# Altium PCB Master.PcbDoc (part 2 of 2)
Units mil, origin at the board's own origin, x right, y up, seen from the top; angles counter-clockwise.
Board outline 11420.03 x 8220.01 mil, 2 copper layers (Top Layer, Bottom Layer); 224 components, 0 nets, 1169 pads, 54 vias.
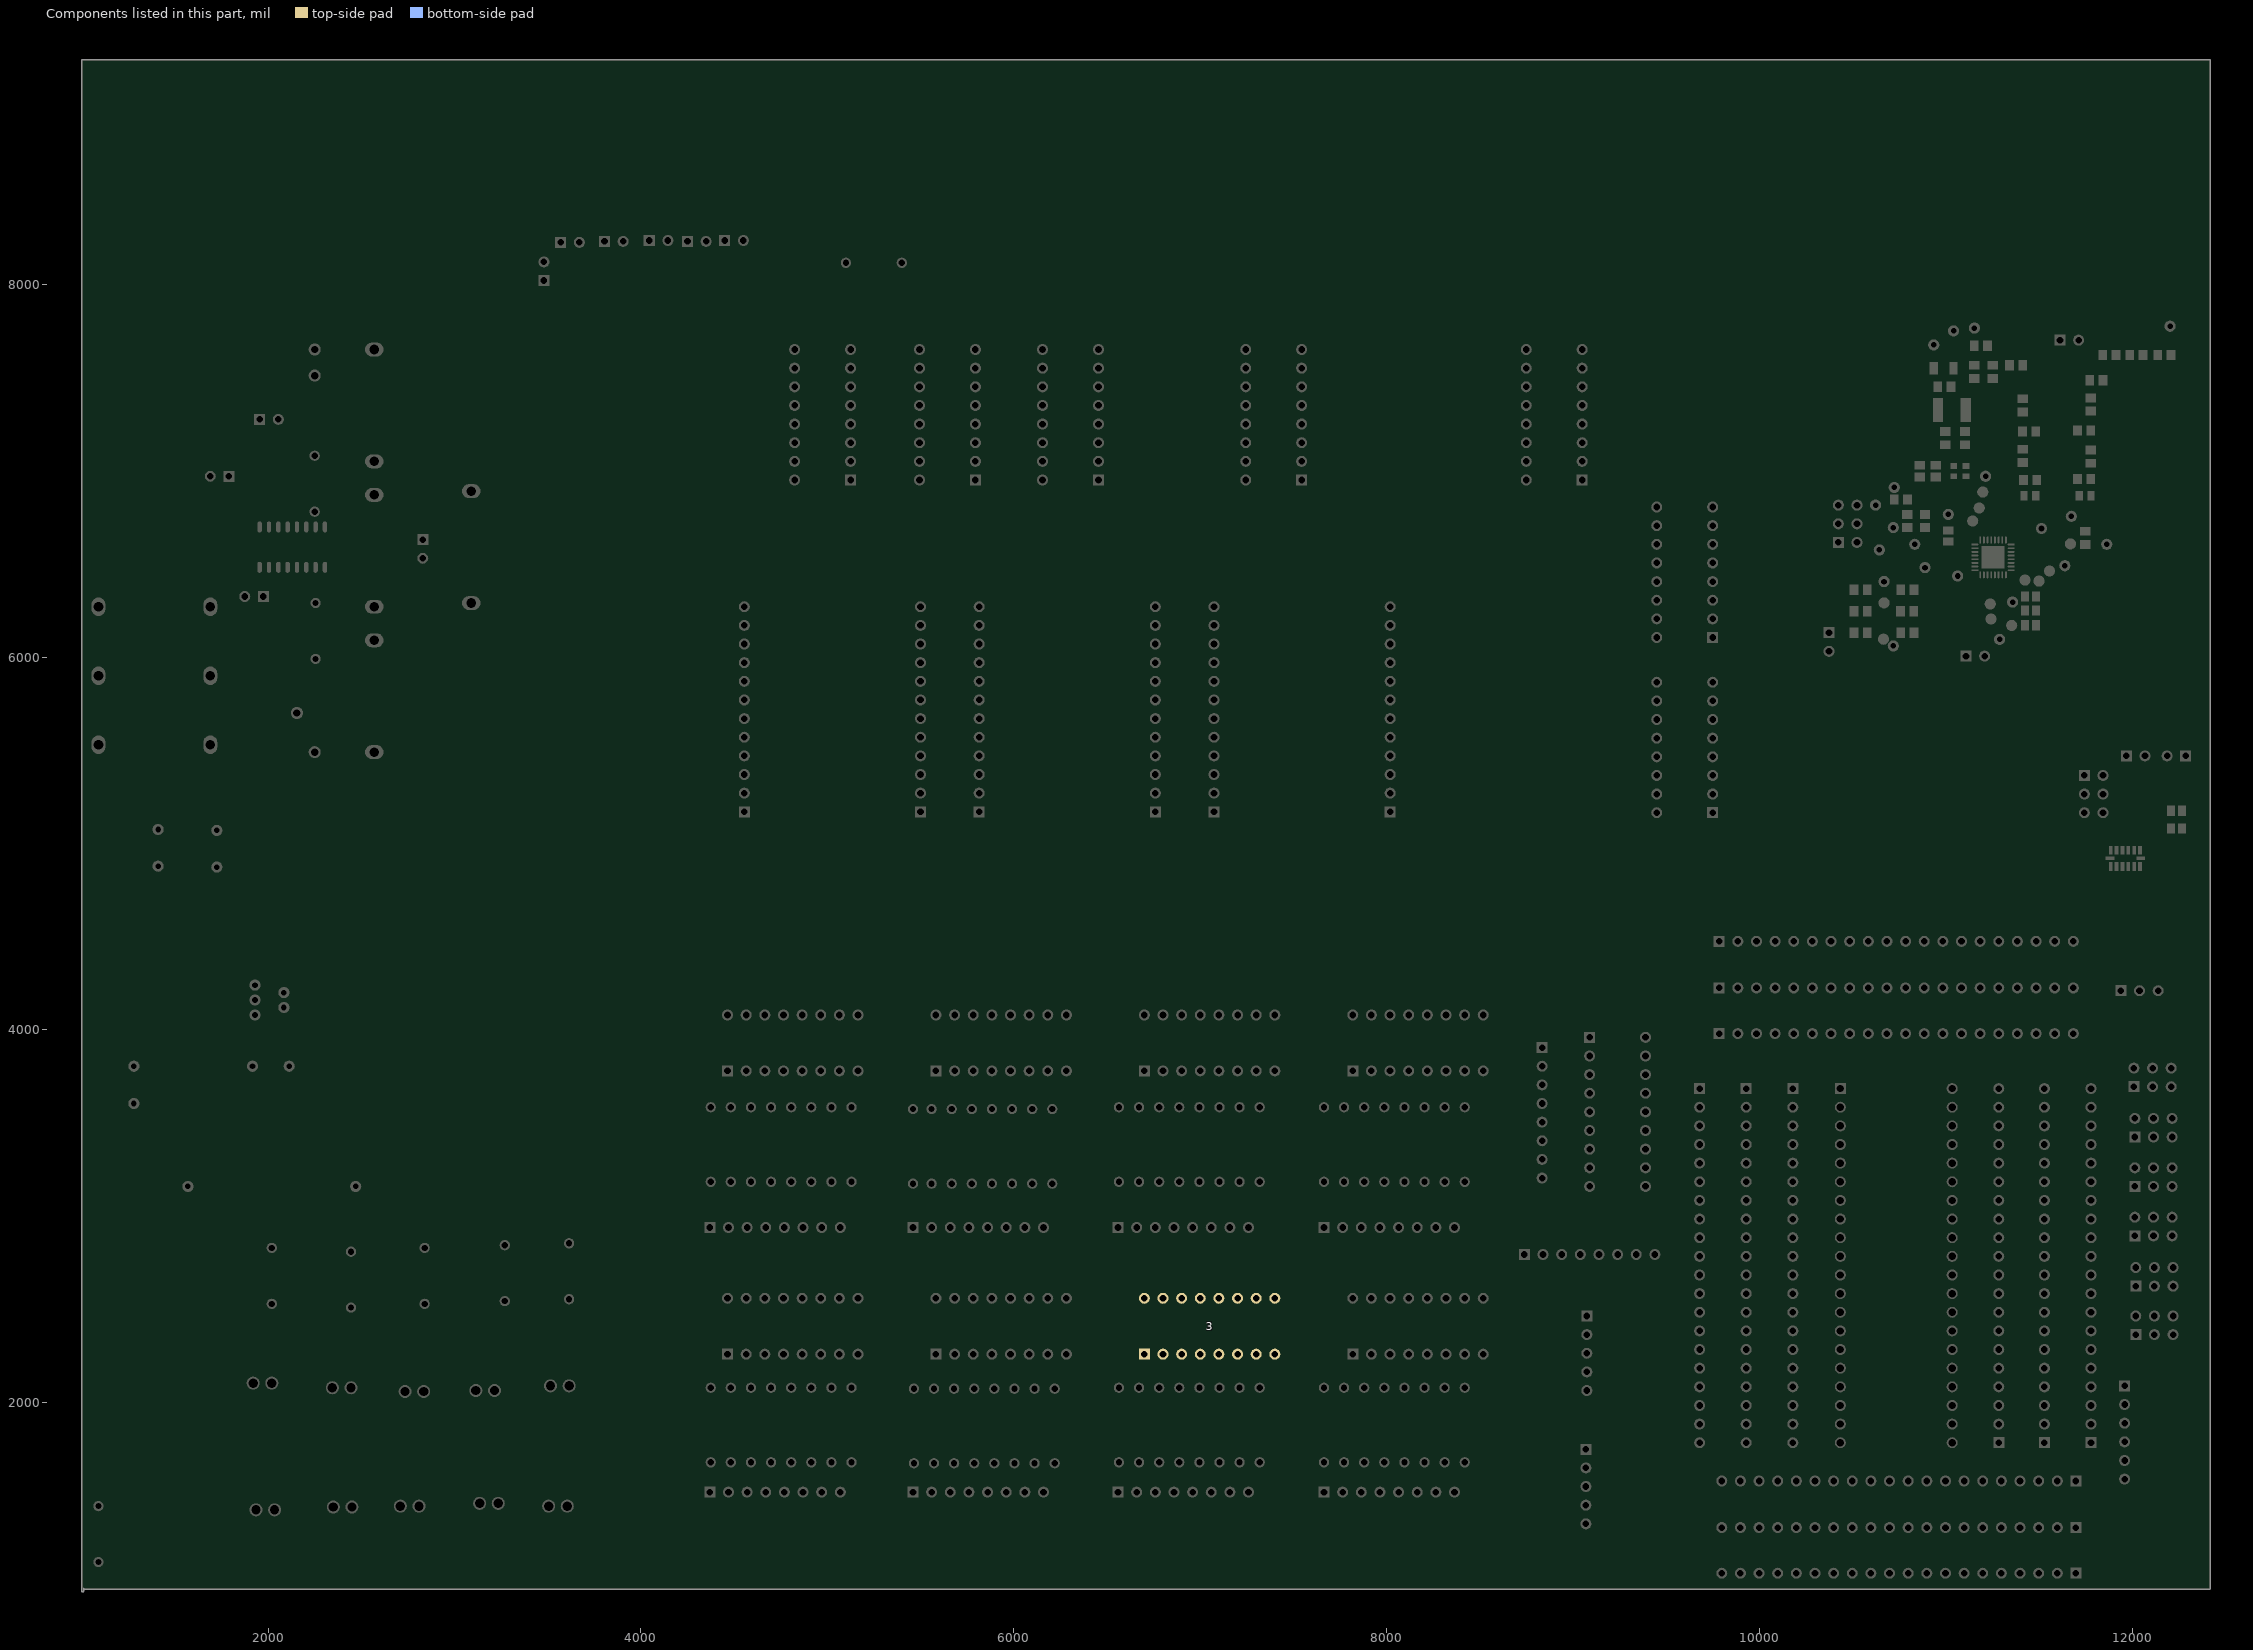
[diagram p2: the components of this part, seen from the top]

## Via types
v1: diameter 50, hole 28, Top Layer to Bottom Layer, 42 vias
v2: diameter 19.68, hole 7.87, Top Layer to Bottom Layer, 9 vias
v3: diameter 40, hole 27, Top Layer to Bottom Layer, 3 vias

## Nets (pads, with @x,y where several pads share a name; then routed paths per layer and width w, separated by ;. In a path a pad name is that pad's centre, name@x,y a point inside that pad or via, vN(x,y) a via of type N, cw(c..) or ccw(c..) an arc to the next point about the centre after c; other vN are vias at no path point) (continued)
copper on no net: | length 666454
  Top Layer w10: 1005,990 1005,9200 12415,9200 12415,1005 ; 1005,5340 2835,5340 2835,2980 ; 1005,5355 3235,5355 3235,7760 1005,7760 ; 1015,1005 12415,1005 ; 1090,5530 1090,5900 1090,6270 1090,6450 1240,6600 1635,6600 1690,6655 ; 1280,3605 1280,3610 ; 1280,3805 1280,3815 ; 1290,3600 1290,3605 ; 1690,5530 1690,5900 1690,6270 1715,6270 1810,6175 2000,6175 2105,6280 2105,6481.73 2105,6698.27 2105,7150 2145,7190 2145,7350 2110,7385 1865,7385 1790,7310 1790,6970 ; 1690,6970 1690,6655 ; 1875,6325 1955,6405 1955,6481.73 ; 1930,4155 1930,4160 ; 1950,7290 1950,6703.27 1955,6698.27 ; 1975,6325 2055,6405 2055,6481.73 ; 2005,6481.73 2005,6692.64 ; 2005,6600 1745,6600 1690,6655 ; 2050,7290 2055,7285 2055,6698.27 ; 2085,4115 2085,4120 ; 2155,5700 2155,6481.73 ; 2155,6698.27 2155,7090 2250,7185 2250,7510 ; 2205,6481.73 2205,6530 2235,6560 2800,6560 2830,6530 2830,6380 2920,6290 3090,6290 ; 2205,6698.27 2205,6640 2235,6610 2275,6610 2305,6640 2305,6698.27 2305,6805 2370,6870 2570,6870 2735,6870 2830,6775 2830,6630 3045,6630 3090,6675 3090,6890 ; 2250,5490 2570,5490 ; 2250,6703.27 2250,6780 2250,7080 2330,7080 2360,7050 2570,7050 ; 2250,7650 2570,7650 ; 2255,6481.73 2255,6290 2255,5990 2350,5990 2450,6090 2570,6090 ; 2305,6481.73 2305,6453.8 2305,6397.93 2305,6370 2405,6270 2570,6270 ; 2350,1440 2360,1440 ; 2425,2830 2445,2810 ; 2485,3580 2485,3585 ; 2710,1445 2725,1445 ; 2820,2810 2840,2830 2855,2845 ; 3480,8020 3678,8020 3855,8197 3855,8275 3907,8327 4048,8327 4100,8275 4100,7995 4790,7305 4839.53,7305 4869.53,7275 4869.53,7225.53 4838.53,7194.53 4800,7194.53 4780.47,7175 4780.47,6994.53 4825,6950 ; 3905,8230 3905,8133.11 4756.56,7281.56 4793.44,7281.56 4825,7250 4760.47,7185.47 4760.47,5775.47 4555,5570 ; 3955,995 9810,995 ; 3985,995 3985,4530 ; 3985,2990 3985,4530 ; 4145,8235 4239,8329 4350,8329 4398,8281 4398,7811 4804,7405 4850,7405 4870,7425 4870,7505 4825,7550 ; 4350,8230 4350,7825 4825,7350 ; 4370,1520 4370,1597 4374.88,1601.88 4374.88,1680 ; 4370,2940 4402.44,2972.44 4374.88,3000 4374.88,3185 ; 4374.88,2080 4374.88,2369.88 4565,2560 ; v1(4410,3980) 4565,3980 4665,4080 ; 4455,5170 4555,5170 ; 4465,2260 4465,2178.76 4482.76,2161 4482.76,2080 ; 4465,3780 4465,3690.76 4482.76,3673 4482.76,3585 ; 4470,1520 4470,1593 4482.76,1605.76 4482.76,1680 ; 4470,2940 4470,3056 4482.76,3068.76 4482.76,3185 ; 4495,5150 4555,5170 ; 4495,5190 4555,5170 ; 4550,8235 4550,7725 4825,7450 ; 4555,5160 4555,5180 ; 4555,5270 5031,5746 5031,7156 5125,7250 ; 4555,5470 4510,5425 4510,5245 4530,5225 5011,5225 5302,5516 5302,6663.27 5634,6995.27 5634,7189 5795,7350 ; 4555,5870 4510,5825 4510,5540 4530,5520 4620,5520 4803,5703 4803,6675 4997,6869 4997,7322 5125,7450 5170,7495 5520,7495 5540,7475 5540,7195 5495,7150 ; 4565,2260 4565,2105.63 4590.63,2080 ; 4565,3780 4565,3610.63 4590.63,3585 ; 4570,1520 4570,1659.37 4590.63,1680 ; 4570,2940 4570,3164.37 4590.63,3185 ; 4665,2260 4665,2113.5 4698.5,2080 ; 4665,3780 4665,3618.5 4698.5,3585 ; 4670,1520 4698.5,1548.5 4698.5,1680 ; 4670,2940 4698.5,2968.5 4698.5,3185 ; 4765,2260 4765,2121.38 4806.38,2080 ; 4765,3780 4765,3626.38 4806.38,3585 ; 4765,4080 4649,4196 4498,4196 4285,3983 4285,2754 4400,2639 4686,2639 4765,2560 4915,2410 5015,2410 5165,2260 5220,2315 ; 4770,1520 4806.38,1556.38 4806.38,1680 ; 4770,2940 4806.38,2976.38 4806.38,3185 ; 4825,7150 4957,7282 4957,7435 5027,7505 5143,7505 5233,7595 5587,7595 5771,7779 6251,7779 6287,7743 6287,7694 6243,7650 6155,7650 ; 4865,2260 4865,2129.25 4914.25,2080 ; 4865,2560 4675,2750 4420,2750 4315,2855 4315,3740 4470,3895 4680,3895 4865,4080 4952,3993 5152,3993 5285,3860 5285,2960 5495,2750 5793.1,2750 5983.1,2560 6180.1,2363 6354,2363 6462,2255 6462,2080 6515,2027 6592,2027 6620,2055 6620,2291 6650,2321 6847,2321 7056,2530 7056,2560 7101.19,2560 6928.19,2733 6538,2733 6505,2766 6505,3259 6619,3373 6619,3798 6751,3930 6951.19,3930 7101.19,4080 ; 4865,3780 4865,3634.25 4914.25,3585 ; 4870,1520 4914.25,1564.25 4914.25,1680 ; 4870,2940 4914.25,2984.25 4914.25,3185 ; 4965,2260 4965,2137.13 5022.13,2080 ; 4965,2560 v1(4965,2766) ; 4965,3780 4965,3642.13 5022.13,3585 ; 4965,4080 5049.53,4164.53 5998.57,4164.53 6083.1,4080 ; 4970,1520 5022.13,1572.13 5022.13,1680 ; 4970,2940 5022.13,2992.13 5022.13,3185 ; 5065,2260 5065,2145 5130,2080 ; 5065,3780 5065,3650 5130,3585 ; v1(5065,5345) 5282,5562 5282,6837 5495,7050 ; 5070,1520 5130,1580 5130,1680 ; 5070,2940 5130,3000 5130,3185 ; 5085,5160 5085,5180 ; v1(5085,6766) 5080,6771 5080,7105 5125,7150 ; v1(5125,5620) 5125,6950 ; 5125,7350 5395,7350 5495,7250 ; 5145,5150 5085,5170 ; 5145,5190 5085,5170 ; 5165,3780 5220,3725 5220,2315 ; 5165,4080 5497,4080 5551.53,4134.53 5728.57,4134.53 5783.1,4080 ; 5185,5170 5085,5170 ; v1(5235,6070) 5235,6914 5421,7100 5550,7100 5590,7140 5590,7345 5795,7550 ; 5300,5170 5400,5170 ; 5340,5150 5400,5170 ; 5340,5190 5400,5170 ; v1(5342,5870) 5342,5524 5065,5247 5065,5112 5132,5045 5132,4915 5174,4873 9663.47,4873 9705.47,4915 9705.47,5970.94 9794.53,6060 9794.53,6425.47 9770,6450 9730,6450 9705,6475 9705,6560 9750,6605 ; 5400,5160 5400,5180 ; v1(5455,5820) 5532,5820 5706,5994 5706,7155 5746,7195 5820,7195 5859.53,7234.53 5859.53,7405 5844.53,7420 5795,7450 ; 5460,1520 5460,1595 5464.88,1599.88 5464.88,1675 ; 5460,2940 5460,3175 ; 5460,3575 5460,3856.9 5683.1,4080 ; 5464.88,2075 5464.88,2341.79 5683.1,2560 ; 5495,7650 v1(5715,7870) ; 5500,5160 5500,5180 ; 5500,5270 5351,5270 5184,5103 5184,5005 5273,4916 9630,4916 9685.47,4971.47 9685.47,6340.47 9750,6405 ; 5500,5470 5395,5575 5395,6684 v1(5568,6857) ; 5500,5570 5572,5570 5677,5465 5677,5158 5714,5121 6320,5121 6436,5005 9489,5005 9604,5120 9604,6683.53 9670,6749.53 9770,6749.53 9794.53,6725 9794.53,6549.53 9750,6505 ; 5500,5770 5670,5770 5728,5828 5728,7084 5744,7100 5855,7100 5967,7212 v1(5967,7689) ; 5500,6070 5672,6242 5672,7193 5784,7305 5829.53,7305 5839.53,7315 5839.53,7394 5838.53,7395 5770,7395 5750,7415 5750,7474 5776,7500 5810,7500 5871.53,7561.53 5871.53,7675 5931.06,7734.53 v1(6236.47,7734.53) ; 5500,6170 5415,6085 5415,5586 5486,5515 5595,5515 5635,5475 5635,5166 5844,4957 9502,4957 9660,5115 9660,6615 9750,6705 ; 5559.88,3175 5559.88,3057.12 5560,3057 5560,2940 ; 5559.88,3575 5583.1,3598.21 5583.1,3780 ; 5560,1520 5560,1591 5572.76,1603.76 5572.76,1675 ; 5560,5150 5500,5170 ; 5560,5190 5500,5170 ; 5572.76,2075 5572.76,2162 5583.1,2172.34 5583.1,2260 ; 5600,5170 5500,5170 ; 5660,1520 5660,1654.37 5680.63,1675 ; 5660,2940 5660,3053 5667.76,3060.76 5667.76,3175 ; 5667.76,3575 5667.76,3669 5683.1,3684.34 5683.1,3780 ; 5680.63,2075 5680.63,2166 5683.1,2168.47 5683.1,2260 ; 5715,5170 5815,5170 ; 5755,5150 5815,5170 ; 5755,5190 5815,5170 ; 5760,1520 5788.5,1548.5 5788.5,1675 ; 5760,2940 5760,3049 5775.63,3064.63 5775.63,3175 ; 5775.63,3575 5775.63,3673 5783.1,3680.47 5783.1,3780 ; 5783.1,2260 5783.1,2169.41 5788.5,2164 5788.5,2075 ; 5795,6950 5750.47,6905.47 5750.47,5859.53 5790,5820 5830,5820 5900,5750 v1(5900,5470) ; 5795,7050 5870,6975 5870,6901 5770.47,6801.47 5770.47,5935 5780.47,5925 6057,5925 6357,5625 6782,5625 6804.53,5647.53 6804.53,5725.47 6760,5770 ; 5815,5160 5815,5180 ; 5815,5370 5876.74,5370 6021.74,5515 6785,5515 6824.53,5554.53 6824.53,6811.47 6758,6878 6758,6947 6455,7250 ; 5815,5470 5879.53,5534.53 5879.53,5675.47 5840,5715 5790,5715 5750,5675 5750,5255 5790,5215 6656,5215 6710,5161 6710,5134 6720,5124 6876,5124 6961,5209 6961,5275 7011,5325 7110,5325 7120,5335 7120,5415 7117,5418 7057.47,5418 7010.47,5465 7010.47,5772.47 7063,5825 7110,5825 7332,6047 7332,7181 7425,7274 7425,7305 7470,7350 7545,7350 ; 5815,5670 5770,5625 5770,5340 5790,5320 6638,5320 6735,5223 6830,5223 6872,5265 6872,7401 6778,7495 6600,7495 6455,7350 ; 5815,5970 6260,6415 6260,7255 6455,7450 ; 5815,6070 5859.53,6114.53 5859.53,6244.53 6230,6615 6230,7417 6318,7505 6539,7505 v1(6617,7583) ; 5815,6270 6200,6655 6200,7480 6270,7550 6455,7550 ; 5860,1520 5896.38,1556.38 5896.38,1675 ; 5860,2940 5883.5,2963.5 5883.5,3175 ; 5883.1,2260 5883.1,2173.28 5896.38,2160 5896.38,2075 ; 5883.1,3780 5883.1,3677.41 5883.5,3677 5883.5,3575 ; 5960,1520 6004.25,1564.25 6004.25,1675 ; 5960,2940 5991.38,2971.38 5991.38,3175 ; 5983.1,2260 5983.1,2096.16 6004.25,2075 ; 5983.1,3780 5983.1,3681.28 5991.38,3673 5991.38,3575 ; 6060,1520 6112.13,1572.13 6112.13,1675 ; 6060,2940 6099.25,2979.25 6099.25,3175 ; 6083.1,2260 6083.1,2104.03 6112.13,2075 ; 6083.1,2560 6338,2814.9 6338,3825.1 6083.1,4080 ; 6083.1,3780 6083.1,3685.16 6099.25,3669 6099.25,3575 ; 6155,7050 6110,7095 6110,7575 6130,7595 6568.84,7595 6607.84,7634 6726,7634 6990.47,7369.53 6990.47,5454.53 7075,5370 ; 6160,1520 6220,1580 6220,1675 ; 6160,2940 6207.13,2987.13 6207.13,3175 ; 6183.1,2260 6183.1,2111.9 6220,2075 ; 6183.1,3780 6183.1,3599.03 6207.13,3575 ; 6283.1,2260 6228.1,2315 6128.1,2315 5883.1,2560 5809.1,2634 5539,2634 5220,2315 ; 6283.1,2560 6338.1,2615 6846.19,2615 6901.19,2560 ; 6283.1,4080 6337.62,4134.53 6846.66,4134.53 6901.19,4080 ; v1(6328,7100) 6475,7100 6685,6890 6685,6145 6760,6070 ; v1(6339,5709) 6288,5760 6288,7241 6347,7300 6580,7300 v1(6735,7455) ; 6345,5160 6345,5180 ; 6405,5150 6345,5170 ; 6405,5190 6345,5170 ; 6445,5170 6345,5170 ; 6455,6950 6455,5975 6760,5670 ; 6455,7050 6528,6977 6528,6202 6760,5970 ; 6455,7150 6760,6845 6760,6270 ; 6560,1520 6560,1597 6564.88,1601.88 6564.88,1680 ; 6560,2940 6560,3060 6564.88,3064.88 6564.88,3185 ; 6560,5170 6660,5170 ; 6564.88,2080 6564.88,2323.69 6801.19,2560 ; 6564.88,3585 6539.66,3610.22 6539.66,3880 6570.6,3910.94 6632.13,3910.94 6801.19,4080 ; v1(6590,3855) 6633,3855 6772,3994 6915.19,3994 7001.19,4080 ; 6600,5150 6660,5170 ; 6600,5190 6660,5170 ; 6660,1520 6660,1593 6672.76,1605.76 6672.76,1680 ; 6660,2940 6660,3056 6672.76,3068.76 6672.76,3185 ; 6660,5160 6660,5180 ; 6672.76,2080 6701.19,2108.43 6701.19,2260 ; 6672.76,3585 6701.19,3613.43 6701.19,3780 ; 6760,1520 6760,1659.37 6780.63,1680 ; 6760,2940 6760,3164.37 6780.63,3185 ; 6760,5160 6760,5180 ; 6760,5270 6844.53,5354.53 6844.53,6912.47 v1(6832,6925) ; v1(6780,8115) 7245,7650 ; 6780.63,2080 6801.19,2100.56 6801.19,2260 ; 6780.63,3585 6801.19,3605.56 6801.19,3780 ; 6820,5150 6760,5170 ; 6820,5190 6760,5170 ; 6860,1520 6888.5,1548.5 6888.5,1680 ; 6860,2940 6888.5,2968.5 6888.5,3185 ; 6860,5170 6760,5170 ; 6888.5,2080 6888.5,2163 6901.19,2175.69 6901.19,2260 ; 6888.5,3585 6888.5,3676 6901.19,3688.69 6901.19,3780 ; 6960,1520 6996.38,1556.38 6996.38,1680 ; 6960,2940 6996.38,2976.38 6996.38,3185 ; 6975,5170 7075,5170 ; 6996.38,2080 6996.38,2167 7001.19,2171.81 7001.19,2260 ; 6996.38,3585 6996.38,3680 7001.19,3684.81 7001.19,3780 ; 7015,5150 7075,5170 ; 7015,5190 7075,5170 ; 7060,1520 7104.25,1564.25 7104.25,1680 ; 7060,2940 7104.25,2984.25 7104.25,3185 ; 7075,5160 7075,5180 ; 7075,5270 7120.54,5270 7135.54,5255 7434,5255 7590,5099 8172,5099 8675,5602 v1(8675,6135) ; 7075,5470 7030.47,5514.53 7030.47,5595 7050.47,5615 7130,5615 7448,5297 7803,5297 7975,5125 8129,5125 8489,5485 8489,6955 8534,7000 9000,7000 9050,6950 ; 7075,5570 7370,5275 7757,5275 v1(7867,5165) ; 7075,5770 7134.97,5770 7440,6075.03 7440,7153.59 7446.41,7160 7446.41,7286.41 7460,7300 7880,7300 8075,7105 8995,7105 9050,7050 ; v1(7084.19,2477) 7184.19,2477 7401.19,2260 ; 7101.19,2260 7101.19,2171.06 7104.25,2168 7104.25,2080 ; 7101.19,3780 7101.19,3683.06 7104.25,3680 7104.25,3585 ; 7160,1520 7212.13,1572.13 7212.13,1680 ; 7160,2940 7212.13,2992.13 7212.13,3185 ; 7201.19,2260 7201.19,2174.94 7212.13,2164 7212.13,2080 ; 7201.19,2560 7287.19,2646 7738,2646 ; 7201.19,3780 7201.19,3687.94 7212.13,3677 7212.13,3585 ; 7245,7150 7364.66,7269.66 7364.66,7644.66 7435,7715 8685,7715 8750,7650 ; 7260,1520 7320,1580 7320,1680 ; 7260,2940 7320,3000 7320,3185 ; 7301.19,2260 7301.19,2178.81 7320,2160 7320,2080 ; 7301.19,3780 7301.19,3691.81 7320,3673 7320,3585 ; 7401.19,2560 7456.19,2615 7964.29,2615 8019.29,2560 ; 7401.19,4080 7532.19,4211 7888.29,4211 8019.29,4080 ; v1(7480,5355) 7460,5375 7460,7140 7501,7181 7501,7206 7545,7250 ; v1(7500,7100) 7500,5690 8020,5170 ; 7545,6950 7545,5945 8020,5470 ; 7545,7050 7613,6982 7613,6177 8020,5770 ; 7545,7150 7884,6811 7884,6206 8020,6070 ; 7605,5160 7605,5180 ; 7664.88,1680 7664.88,1599.12 7665,1599 7665,1520 ; 7664.88,2080 7664.88,2305.6 7919.29,2560 ; 7664.88,3185 7664.88,3062.12 7665,3062 7665,2940 ; 7664.88,3585 7664.88,3825.6 7919.29,4080 ; 7665,5150 7605,5170 ; 7665,5190 7605,5170 ; 7705,5170 7605,5170 ; 7765,1520 7765,1596 7772.76,1603.76 7772.76,1680 ; 7765,2940 7765,3058 7772.76,3065.76 7772.76,3185 ; 7772.76,2080 7772.76,2213.47 7819.29,2260 ; 7772.76,3585 7819.29,3631.53 7819.29,3780 ; 7865,1520 7865,1592 7880.63,1607.63 7880.63,1680 ; 7865,2940 7865,3054 7880.63,3069.63 7880.63,3185 ; 7880.63,2080 7919.29,2118.66 7919.29,2260 ; 7880.63,3585 7919.29,3623.66 7919.29,3780 ; v1(7917,5336) 8006,5425 8055,5425 8065,5435 8065,7005 8110,7050 8750,7050 ; 7965,1520 7988.5,1543.5 7988.5,1680 ; 7965,2940 7988.5,2963.5 7988.5,3185 ; 7988.5,2080 8019.29,2110.78 8019.29,2260 ; 7988.5,3585 8019.29,3615.78 8019.29,3780 ; 8065,1520 8096.38,1551.38 8096.38,1680 ; 8065,2940 8096.38,2971.38 8096.38,3185 ; 8096.38,2080 8119.29,2102.91 8119.29,2260 ; 8096.38,3585 8119.29,3607.91 8119.29,3780 ; 8119.29,2560 8204.29,2475 8304.29,2475 8519.29,2260 ; 8165,1520 8204.25,1559.25 8204.25,1680 ; 8165,2940 8204.25,2979.25 8204.25,3185 ; 8204.25,2080 8204.25,2162 8219.29,2177.03 8219.29,2260 ; 8204.25,3585 8204.25,3674 8219.29,3689.03 8219.29,3780 ; 8219.29,2560 8273.86,2505.42 8316.29,2505.42 8496.48,2325.24 8574,2325.24 8574,1421 8700,1295 9100,1295 9125,1320 9125,1395 9070,1450 9154.53,1534.53 9154.53,2285.47 9075,2365 8685,2755 8685,4197 8652,4230 8369.29,4230 8219.29,4080 ; 8265,1520 8312.13,1567.13 8312.13,1680 ; 8265,2940 8312.13,2987.13 8312.13,3185 ; 8312.13,2080 8312.13,2166 8319.29,2173.16 8319.29,2260 ; 8312.13,3585 8312.13,3678 8319.29,3685.16 8319.29,3780 ; 8319.29,4080 8374.29,4135 8548,4135 8604,4079 8604,2520 8589.31,2505.31 8373.97,2505.31 ; 8365,1520 8420,1575 8420,1680 ; 8365,2940 8420,2995 8420,3185 ; 8419.29,2260 8419.29,2169.71 8420,2169 8420,2080 ; 8419.29,2560 8574,2714.71 8574,3925.29 8419.29,4080 ; 8419.29,3780 8419.29,3682.71 8420,3682 8420,3585 ; 8740,2795 8740,3030.47 8889.53,3180 8889.53,3659.53 9090,3860 ; v1(8750,6105) 8750,6950 ; 8750,7150 8685,7215 8685,7575 8705,7595 8775,7595 8795,7615 8795,7825 v1(8750,7870) ; 8750,7250 8795,7295 9075,7295 9115,7255 9115,6939 ; 8750,7550 8895,7405 9062,7405 9553,6914 9553,6808 9450,6705 9476.28,6678.72 9490.8,6678.72 9514.53,6655 9514.53,5829.53 9450,5765 ; v1(8776,5865) 8776,5657 9313,5120 9470,5120 9517,5167 v1(9517,5265) ; 8835,3205 8780,3260 8780,3955 8850,4025 9150,4025 9218,3957 9218,3832 9390,3660 ; 8840,2795 8840,3055.48 8919.53,3135.01 8919.53,3489.53 9090,3660 ; 8940,2795 8940,3103.47 8949.53,3113 8949.53,3319.53 9090,3460 ; v1(8990,6105) 8990,5625 9450,5165 ; 9040,2795 9040,3138 9031,3147 9031,3201 9090,3260 ; 9050,7250 9095,7205 9095,5578 v1(9333,5340) ; 9050,7350 9159,7241 v1(9159,6955) ; 9050,7650 9750,6950 9750,6805 9814.53,6740.47 9814.53,5929.53 9750,5865 ; 9070,1350 8986,1434 8986,2176 9075,2265 8974,2366 8513.29,2366 8373.97,2505.31 ; 9070,1650 9124.53,1704.53 9124.53,2015.47 9075,2065 ; 9070,1750 9016,1804 9016,2106 9075,2165 ; 9340,2795 9340,2908 9335,2913 9335,3505 9390,3560 ; 9390,3760 9445,3705 9445,3138 9440,3133 9440,2795 ; 9450,5365 9365.47,5449.53 9365.47,6735.47 9407.97,6777.97 9422.97,6777.97 9450,6805 ; 9450,5465 9495,5420 9495,5345 9470,5320 9430,5320 9115,5635 9115,6939 ; 9450,5565 9495,5610 9495,5695.47 9470,5720.47 9430,5720.47 9405.47,5745 9405.47,5785 9440.47,5820 9470,5820 9494.53,5844.53 9494.53,6335.47 9470,6360 9430,6360 9405.47,6384.53 9405.47,6460.47 9450,6505 ; 9450,5665 9385.47,5729.53 9385.47,6540.47 9450,6605 ; 9450,6405 9494.53,6449.53 9494.53,6632.47 9467,6660 9430,6660 9405,6685 9405,6735 9425,6755 9464.53,6755 9495,6785.47 9495,6825 9470,6850 9204,6850 9115,6939 ; 9545,995 9560,995 ; 9545,4530 9560,4530 ; v1(9555,6061) 9558,6058 v1(9558,5365) ; 9560,1000 9560,4530 ; 10220,5920 12250.12,5920 12250.12,6950 12250.12,7850 10155,7850 10155,5920 10230,5920 ; 10374.25,6130.87 10508.82,6130.87 10508.82,6245.87 10508.82,6360.87 ; 10579.68,6130.87 10669.25,6130.87 ; 10579.68,6245.87 10669.68,6245.87 ; 10579.68,6360.87 10669.25,6360.87 ; 10624.25,6815 10624.25,7028.94 10799.25,7028.94 ; 10644.25,6575 10644.25,6545.16 10849.25,6545.16 ; 10666.75,6095.87 10702.62,6060 10719.25,6060 10729.25,6060 ; 10669.25,6095.87 10669.25,6130.87 ; v1(10669.25,6205.87) 10669.68,6205.87 10669.68,6245.87 ; 10669.68,6290.87 10669.68,6245.87 ; 10669.68,6405.87 10669.25,6405.87 10669.25,6405 10669.25,6360.87 ; 10709.25,6694.57 10719.25,6694.57 10794.25,6694.57 10794.25,6635 10594.25,6635 10594.25,6525.16 11156.81,6525.16 ; 10723.82,6845 10724.25,6845 10724.25,6910 ; 10751.75,6110.87 10751.75,6130.87 ; 10751.75,6155.87 10751.75,6130.87 ; 10758.39,6245.87 10669.68,6245.87 ; 10758.82,6130.87 10751.75,6130.87 ; 10758.82,6360.87 10669.25,6360.87 ; 10794.69,6845 10794.25,6845 10794.25,6765.43 10889.25,6765.43 11014.25,6765.43 11014.25,6685 ; 10824.25,6544.84 11156.81,6544.84 ; 10829.25,6360.87 10829.68,6360.87 10829.68,6130.87 ; 10834.25,6605 10869.25,6605 10869.25,6564.53 10899.25,6564.53 ; 10860.95,6965.94 10860.95,6924.88 11154.25,6924.88 11154.25,7025 ; 10889.25,6480 11004.25,6480 11004.25,6505.47 11156.81,6505.47 ; 10899.25,6690 10899.25,6564.53 ; 10935.24,7545 10935.24,7450 10957.95,7450 10957.95,7325 10958.58,7325 ; 10936.1,7550 10936.1,7675 10936.1,7690 ; 10947.56,6965.94 10945.69,6967.31 10860.95,7028.94 10799.25,7028.94 ; 10947.56,6969.88 11044.25,6969.88 11109.25,6969.88 ; 10947.56,7028.94 10947.56,7025 11044.25,7025 11044.25,7070 11283.46,7070 ; 10998.39,7210.43 11103.39,7210.43 ; 11014.25,6620.47 11014.25,6584.21 11156.81,6584.21 v2@11205.04,6584.21 ; 11014.25,6679.53 11014.25,6685 ; 11028.82,7450 11043.39,7450 11043.39,7545 11041.54,7545 ; 11042.4,7550 11042.4,7750 10799.25,7750 10799.25,7139.57 ; 11064.25,6425 11064.25,6435 11064.25,6485.79 11156.81,6485.79 ; 11103.39,7139.57 10998.39,7139.57 10799.25,7139.57 ; 11108.19,7325 11108.19,7210.43 11103.39,7210.43 ; 11109.25,6005 11109.25,6466.1 11156.81,6466.1 ; 11109.25,7025 11154.25,7025 ; 11139.25,6740 11139.25,6708.9 11185.35,6708.9 11185.35,6628.5 ; 11153.39,7494.57 11253.39,7494.57 ; 11153.39,7565.43 11152.95,7565.43 11152.95,7670 11154.25,7670 11154.25,7765 11154.25,7780 ; 11156.81,6564.53 10899.25,6564.53 ; 11156.81,6603.9 11085.35,6603.9 11085.35,6685 11014.25,6685 ; 11199.25,6885 11224.72,6885 11224.72,6628.5 ; v2@11205.04,6535 11205.04,6441.5 11205.04,6380 11184.25,6380 11184.25,6095 11289.25,6095 11483.78,6095 11483.78,6170 11483.78,6250 11483.78,6325 ; 11205.04,6628.5 11205.04,6795 ; 11223.82,7670 11223.82,7780 12208.82,7780 12208.82,7620 12208.39,7620 ; 11224.72,6441.5 11224.72,6535 ; 11229.25,6970 11244.41,6970 11244.41,6628.5 ; 11243.39,6205 11282.91,6205 ; 11244.41,6441.5 11244.41,6535 v2(11254.25,6535) ; 11253.39,7565 11342.95,7565 ; 11263.78,7025 11154.25,7025 ; 11264.09,6280 11264.09,6441.5 ; 11264.09,6628.5 11264.09,7025 ; 11283.78,6205 11283.78,6441.5 ; 11283.78,6628.5 11283.78,7070 ; 11303.15,7105 11174.25,7105 11174.25,7210 11103.39,7210 11103.39,7210.43 ; 11303.46,6441.5 11303.46,6170 11424.72,6170 ; 11303.46,6628.5 11303.46,7105 ; 11323.15,6441.5 11323.15,6295 ; 11323.15,6628.5 11323.15,6765 11483.39,6765 11483.39,6865 ; 11351.69,6466.1 11351.69,6465 11424.25,6465 11424.25,6325 ; 11351.69,6485.79 11489.25,6485.79 11489.25,6407.44 11500.98,6407.44 ; 11351.69,6505.47 11561.81,6505.47 11561.81,6466.73 ; 11351.69,6525.16 11624.25,6525.16 11624.25,6525 11639.25,6525 11639.25,6490 11639.25,6480 ; 11351.69,6544.84 12058.82,6544.84 12058.82,7620 12137.95,7620 12143.39,7620 ; 11351.69,6564.53 11749.25,6564.53 ; 11351.69,6584.21 11604.25,6584.21 ; 11351.69,6603.9 11404.25,6603.9 11404.25,6690 11514.25,6690 11559.25,6690 11559.25,6950 ; 11369.25,6295 11359.25,6295 11323.15,6295 ; 11413.39,6865 11413.39,6950 ; 11413.39,7044.57 11413.39,6950 ; 11413.39,7115.43 11413.39,7210 11412.95,7210 11412.95,7314.57 11413.39,7314.57 ; 11413.39,7385.43 11413.39,7560 ; 11413.82,7560 11413.39,7560 ; 11417.95,6950 11413.39,6950 ; 11424.72,6250 11323.15,6250 11323.15,6295 ; 11483.82,7210 11559.25,7210 ; 11488.82,6950 11559.25,6950 ; 11570,4640 11570,5670 11590,5670 ; 11580.12,5670 12415,5670 ; 11604.25,6584.53 11604.25,6865 11716.89,6865 ; 11613.39,7700 11413.39,7700 11413.39,7560 ; 11669.25,6607.44 11749.25,6607.44 11749.25,6604.57 11749.25,6564.53 ; 11674.25,6755 11749.25,6755 11749.25,6675.43 ; v1(11704.25,5015) 11885.51,5015 11885.51,4963.31 ; 11707.95,6955 11707.95,6950 11559.25,6950 ; 11707.95,7215 11707.95,7210 11559.25,7210 ; 11713.39,7700 11778.39,7700 11778.39,7390.43 ; 11744.25,5265 11644.25,5265 11644.25,4920 11881.57,4920 ; 11772.95,7485 11774.25,7485 ; 11778.39,7039.57 11778.82,7039.57 11778.82,6955 11778.82,6865 11779.88,6865 ; 11778.39,7110.43 11778.82,7110.43 11778.82,7215 11778.39,7215 11778.39,7319.57 ; 11842.95,7620 11843.82,7620 11843.82,7480 ; 11844.25,5265 11919.25,5265 11919.25,4963.31 11917.01,4963.31 ; 11864.25,6605 11864.25,6564.53 11749.25,6564.53 ; 11884.25,4876.69 11885.51,4876.69 11885.51,4755 12264.25,4755 12264.25,5080 12268.78,5080 ; 11913.82,7620 11987.95,7620 ; 11914.25,4876.69 11917.01,4876.69 ; 11920.2,4876.69 11920.2,4920 11980,4920 ; 11940,4210 11940,3765 12010,3695 12045.47,3659.53 12045.47,3639.53 12060,3625 12060,3470 12015,3425 11970.47,3380.47 11970.47,3204.53 12015,3160 11970.47,3115.47 11970.47,2939.53 12015,2895 11975,2855 11975,2670 12020,2625 11975.47,2580.47 11975.47,2409.53 12020,2365 ; 11948.5,4755 11948.5,4876.69 ; 11948.5,4963.31 11979.25,4963.31 ; 11960,1790 12005,1835 12005,2001 12004,2002 12004,2011.47 11970,2045.47 11915.47,2045.47 11915.47,2134.53 12021.94,2241 12150,2241 12230,2321 12250,2321 12264.53,2335.53 12264.53,2750 12215,2799.53 12215,2895 ; 11960,1990 11924.53,2025.47 11895.47,2025.47 11895.47,2170.47 12022.04,2297.04 12166.04,2297.04 12170,2301 12170,3304.53 12191,3325.53 12191,3401 12215,3425 ; 11960,2090 12035,2090 12190.28,2245.28 12227.42,2245.28 12284.53,2302.39 12284.53,2791.5 12265,2811.03 12265,3640 12210,3695 ; v1@11962.56,5170 11979.25,5153.31 11979.25,4963.31 ; 11969.25,5465 11969.25,5405 11969.25,5385 12011.5,5385 12011.5,5285 12011.5,4963.31 ; v1(11999.25,4805) 11980,4805 11980,4876.69 ; 12011.5,4876.69 11980,4876.69 ; 12040,4210 12040,4001 12088,3953 12088,3817 12110,3795 12065.47,3750.47 12065.47,3650 12115,3600.47 12115,3525 ; 12042.99,4755 12042.99,4876.69 ; 12042.99,4963.31 12042.99,5385 12074.25,5385 12074.25,5465 ; 12046.93,4920 v1(12144.25,4920) ; 12120,2365 12090,2365 12075.47,2379.53 12075.47,2490.47 12120,2535 12120,2625 12075,2670 12075,2855 12115,2895 12115,2925.47 12070.47,2970 12070.47,3039.53 12115,3084.06 12115,3160 12070.47,3204.53 12070.47,3380.47 12115,3425 12160,3470 12160,3645 12110,3695 12155,3740 12155,3982 12140,3997 12140,4210 ; v1@12124.25,4805 v1(12144.25,4805) 12209.25,4805 12209.25,5080 ; 12187.99,5470 12187.99,5400 12209.25,5400 12209.25,5175 ; 12209.72,5080 12209.72,5175 ; 12274.25,5080 12274.25,5400 12287.99,5400 12287.99,5470 ; 3985,4530 9560,4530 ; 3985,4530 9560,4530 ; 6083.1,4080 6167.62,4164.53 7116.66,4164.53 7201.19,4080 7607,3674.19 7607,2777 7738,2646 ; 7738,2646 8233.29,2646 8319.29,2560 8373.97,2505.31 ; 9560,4530 9560,4640 12415,4640 12415,1005 ; 10669.25,6130.87 10751.75,6130.87 ; 10799.25,7028.94 10799.25,7139.57 ; 11559.25,6950 11559.25,7210 ; 11979.25,4963.31 11980,4963.31 11980,4920 ; 11980,4876.69 11980,4920 ; 1005,995 1005,2980 3940,2980 3940,995 1005,995 ; 3380,4715 3380,8640 9975,8640 9975,4715 3380,4715
  Top Layer w20: 1090,1445 1090,1740 1305,1740 ; 1100,1155 1380,1155 1380,1610 v3(1380,1690) ; 1290,1740 v3(1380,1740) ; v3(1380,1790) 1525,1790 ; 1525,1795 1665,1655 1665,1415 1920,1415 1975,1360 2270,1360 2350,1440 ; 1920,2105 1920,1530 2025,1425 ; 2020,2105 2020,2530 ; 2020,2830 2425,2830 ; 2345,2080 2345,1545 2450,1440 ; 2360,1440 2360,1310 2575,1310 2710,1445 ; 2445,2080 2445,2510 ; 2445,2810 2675,2810 ; 2675,2915 2675,2810 ; 2725,1445 2725,1395 2780,1340 2914.47,1340 2924.47,1330 2934.82,1330 2999.82,1395 3070,1395 3135,1460 3135,1395 3190,1340 3400,1340 3505,1445 ; 2735,2060 2735,1520 2810,1445 ; 2820,2810 2675,2810 ; 2835,2060 2835,2525 ; 2855,2845 3270,2845 3605,2845 ; 3115,2065 3115,1580 3235,1460 ; 3215,2065 3215,2490 3270,2545 ; 3515,2090 3515,1535 3605,1445 ; 3615,2090 3615,2555
  Top Layer w30: 1155,4320 1155,4640 1560,4640 1560,4875 ; 1160,4290 1280,4290 1280,3805 ; 1160,4340 1405,4340 1405,4155 1930,4155 ; 1245,5235 1480,5235 1480,5075 ; 1290,3600 1290,3155 1555,3155 ; 1290,3605 1505,3605 1505,3815 1505,3995 2180,3995 2180,4200 2085,4200 ; 1410,4878.15 1700,4878.15 ; 1410,5075 1700,5075 ; 1725,5070 1845,5070 1845,4240 1930,4240 ; 2085,4120 2010,4120 2010,4305 2605,4305 2605,3585 2485,3585 ; 2470,3160 2470,3410 2113.43,3410 2113.43,3810 2485,3810 2485,3580
  Bottom Layer w10: 2015,2825 2030,2810 ; 2820,2810 2840,2830 2855,2845 ; 3480,8120 4290,8120 4295,8115 5100,8115 ; 3570,8225 3670,8225 3737,8158 5120,8158 5143,8135 5143,7668 ; 3605,2845 3615,2855 ; 3805,8230 3905,8230 ; 4045,8235 4145,8235 ; 4250,8230 4350,8230 ; 4374.88,3585 4360,3585 4360,4105 4400,4145 4500,4145 4565,4080 ; v1(4410,3980) 4410,3713 5901,3713 5938,3676 5938,3126 6000,3064 7246,3064 7469,2841 8238.29,2841 8519.29,2560 ; 4450,8235 4550,8235 ; 4465,2560 4520,2615 5010,2615 5065,2560 5120,2505 5528.1,2505 5583.1,2560 5638.1,2505 6128.1,2505 6183.1,2560 6242.1,2501 6642.19,2501 6701.19,2560 6756.19,2615 7246.19,2615 7301.19,2560 7356.19,2505 7764.29,2505 7819.29,2560 7874.29,2615 8364.29,2615 8419.29,2560 8474.29,2505 8574,2505 8609,2540 9100,2540 9160,2480 9160,1359 9096,1295 9015,1295 9015,1750 9070,1750 ; 4465,4080 4520,4025 5010,4025 5065,4080 5124,4021 5524.1,4021 5583.1,4080 5638.1,4135 6128.1,4135 6183.1,4080 6238.1,4025 6646.19,4025 6701.19,4080 6921.19,4300 7081.19,4300 7301.19,4080 7356.19,4025 7764.29,4025 7819.29,4080 8042.29,4303 8196.29,4303 8419.29,4080 8617.29,4278 9072,4278 9390,3960 ; 4555,5170 4510,5215 4510,6095 4530,6115 4580,6115 4600,6135 4600,6195 4575,6220 4533,6220 4510.47,6242.53 4510.47,6937.47 4773,7200 5328,7200 5428,7300 5510,7300 5525,7285 5760,7285 5795,7250 ; 4555,5370 5027,5370 5042.83,5385.83 5097,5385.83 5112.83,5370 5500,5370 5815,5370 ; 4555,5670 5500,5670 5815,5670 ; 4555,5770 5405,5770 v1(5455,5820) ; 4555,5870 4605,5920 5830,5920 5860,5950 5860,5995 5840,6015 5790,6015 5770,6035 5770,6195 5790,6215 6323,6215 6715,5823 8816,5823 8858,5865 9450,5865 ; 4555,5970 5500,5970 5815,5970 ; 4555,6070 v1(5235,6070) ; 4555,6170 4528.72,6196.28 4490.47,6215 4490.47,7326.47 4759,7595 5028.21,7595 5073.21,7550 5125,7550 ; 4555,6270 5500,6270 5815,6270 ; 4665,2560 4851,2374 8984,2374 9075,2465 9130,2410 9130,1610 9070,1550 ; 4825,6950 4870,6905 5450,6905 5495,6950 5540,6905 6110,6905 6155,6950 6222.98,6882.02 7177.02,6882.02 7245,6950 7290,6905 8705,6905 8750,6950 ; 4825,7050 4875,7100 5566,7100 5671,6995 6762,6995 v1(6832,6925) ; 4825,7250 4780,7295 4780,7375 4800,7395 4959,7395 5004,7350 5125,7350 ; 4825,7350 4870,7305 5265,7305 5310,7350 5495,7350 5540,7305 6110,7305 6155,7350 6200,7305 7200,7305 7245,7350 7290,7305 8705,7305 8750,7350 8895,7205 9291,7205 9383,7113 9383,6572 9450,6505 ; 4825,7450 4953,7450 4998,7405 5450,7405 5495,7450 5540,7405 6110,7405 6155,7450 6200,7405 7200,7405 7245,7450 7290,7405 8705,7405 8750,7450 8900,7300 9390,7300 9495,7195 9495,6650 9450,6605 ; 4825,7550 4870,7505 5450,7505 5495,7550 5540,7505 6110,7505 6155,7550 6200,7505 6828,7505 6873,7550 7245,7550 7372,7550 7417,7505 8705,7505 8750,7550 ; 4825,7650 5013.47,7650 5058,7605.47 6559.47,7605.47 6577,7623 7151,7623 7222.53,7694.53 7280.47,7694.53 7351,7624 7479,7624 7503,7600 8795,7600 8991,7404 9750,7404 9795,7359 9795,6275 9775,6255 9500,6255 9450,6305 ; v1(4965,2766) 5877.1,2766 6083.1,2560 ; v1(5065,5345) 5190,5220 6710,5220 6760,5170 ; v1(5085,6766) 6127.11,6766 6723.11,6170 6760,6170 ; v1(5125,5620) 6710,5620 6760,5570 ; 5125,7050 5075,7000 4805,7000 4780,6975 4780,6775 4830,6725 5905,6725 6760,5870 ; 5165,2560 5220,2615 5728.1,2615 5783.1,2560 ; 5165,3780 5315,3930 5733.1,3930 5883.1,4080 6099.1,3864 6199.1,3864 6283.1,3780 6362.1,3859 7322.19,3859 7322.19,3855 ; v1(5342,5870) 5500,5870 ; 5400,8115 v1(6780,8115) ; 5495,7150 5622,7150 5667,7105 6110,7105 6155,7150 ; 5495,7250 5540,7205 5953,7205 5998,7250 6155,7250 6282,7250 6327,7205 7200,7205 7245,7250 7290,7205 8705,7205 8750,7250 ; 5500,5170 5564.53,5105.47 7746.01,5105.47 7957,5316.46 9309.46,5316.46 v1(9333,5340) ; v1(5568,6857) 9061,6857 v1(9159,6955) ; v1(5715,7870) v1(8750,7870) ; 5795,7150 5927,7150 5975,7198 6230,7198 v1(6328,7100) ; 5815,5170 5859.53,5125.47 7250.47,5125.47 v1(7480,5355) ; 5815,5270 5960,5415 7400,5415 7420,5435 7560,5435 7580,5415 9700,5415 9750,5465 ; 5815,5570 5865,5520 9705,5520 9750,5565 ; 5815,5770 5876,5709 v1(6339,5709) ; 5815,5870 6491,5870 6736,5625 8102,5625 8192,5715 9700,5715 9750,5665 ; 5815,6170 6270,6170 6715,5725 8106,5725 8162,5781 9376,5781 9405,5810 9528,5810 9573,5765 9750,5765 ; v1(5900,5470) 6760,5470 ; v1(5967,7689) 6075,7797 9053,7797 9114.53,7735.47 9114.53,7514.53 9050,7450 ; 5983.1,4080 6133.1,3930 6951.19,3930 7101.19,4080 ; v1(6236.47,7734.53) 9034.47,7734.53 9094.53,7674.47 9094.53,7594.53 9050,7550 ; 6283.1,2260 6547.1,1996 7350,1996 7401.19,2047.19 7401.19,2260 7456.19,2315 8464.29,2315 8519.29,2260 8714.29,2065 9075,2065 ; v1(6590,3855) 7322.19,3855 ; v1(6617,7583) 6629,7595 7428,7595 7473,7550 7545,7550 ; v1(6735,7455) 6828,7455 6871,7498 7372,7498 7420,7450 7545,7450 ; 6760,5370 7075,5370 7385,5370 7430,5415 7531.46,5415 7570,5376.46 7939,5376.46 7945.46,5370 8020,5370 ; 6760,5670 7075,5670 8020,5670 ; 6760,5970 7075,5970 8020,5970 ; 6760,6270 7075,6270 8020,6270 ; 7001.19,2560 v1(7084.19,2477) ; 7075,5170 7235,5170 7460,5395 7520,5395 7579,5336 v1(7917,5336) ; 7075,5870 7125,5920 9503.21,5920 9595,6011.79 9595,6086.89 9713.11,6205 9750,6205 ; 7075,6070 6921,6224 6726,6224 6715,6235 6715,6295 6743,6323 8605,6323 9199,6917 9199,7001 9050,7150 ; 7075,6170 7125,6220 9225,6220 9360,6355 9700,6355 9750,6305 ; 7101.19,2560 7251.19,2410 8069.29,2410 8219.29,2560 ; 7245,7050 7450,7050 v1(7500,7100) ; v1(7867,5165) 7957,5075 8499,5075 8634,5210 9770,5210 9814.53,5254.53 9814.53,6040.47 9750,6105 ; 8020,5270 8735,5270 8740,5265 9450,5265 ; 8020,5570 8735,5570 8785,5620 9770,5620 9794.53,5644.53 9794.53,5785 9770,5809.53 9730,5809.53 9705,5834.53 9705,6150 9790,6150 9839,6101 9839,5203 9801,5165 9750,5165 ; 8020,5870 8771,5870 v1(8776,5865) ; 8020,6170 8133,6057 9551,6057 v1(9555,6061) ; v1(8675,6135) 8710,6170 9415,6170 9450,6205 ; v1(8750,6105) v1(8990,6105) 9450,6105 ; 8835,3305 8685,3155 8685,2751 8725,2711 9451,2711 9495,2755 9495,3355 9390,3460 ; 8835,3405 8963,3277 8963,3204 9100,3067 9197,3067 9390,3260 ; 8835,3505 9016,3324 9016,3234 9090,3160 ; 8835,3605 9060,3380 9090,3380 9090,3360 ; 8835,3705 8945,3705 9090,3560 ; 8835,3805 8880,3760 9090,3760 ; 8835,3905 8890,3960 9090,3960 ; 9050,7650 9005,7695 7590,7695 7545,7650 7480.47,7714.53 6519.53,7714.53 6455,7650 6250.31,7650 6205.31,7695 6054.15,7695 6007.6,7648.45 5929.15,7648.45 5927.6,7650 5795,7650 5750,7695 5170,7695 5143,7668 ; 9140,2795 9390,3045 9390,3160 ; 9240,2795 9445,3000 9445,3305 9390,3360 ; 9390,3860 9232.21,4017.79 8757.07,4017.79 8519.29,3780 8369.29,3930 8269.29,3930 8119.29,4080 7969.29,3930 7551.19,3930 7401.19,3780 ; v1(9517,5265) 9750,5265 ; v1(9558,5365) 9750,5365 ; 9680,1785 9930,1785 10180,1785 10435,1785 ; 9680,1885 9930,1885 10180,1885 10435,1885 ; 9680,1985 9930,1985 10180,1985 10435,1985 ; 9680,2085 9930,2085 10180,2085 10435,2085 ; 9680,2185 9930,2185 10180,2185 10435,2185 ; 9680,2285 9930,2285 10180,2285 10435,2285 ; 9680,2385 9930,2385 10180,2385 10435,2385 ; 9680,2485 9930,2485 10180,2485 10435,2485 ; 9680,2585 9930,2585 10180,2585 10435,2585 ; 9680,2685 9930,2685 10180,2685 10435,2685 ; 9680,2785 9930,2785 10180,2785 10435,2785 ; 9680,2885 9930,2885 10180,2885 10435,2885 ; 9680,2985 9930,2985 10180,2985 10435,2985 ; 9680,3085 9930,3085 10180,3085 10435,3085 ; 9680,3185 9930,3185 10180,3185 10435,3185 ; 9680,3285 9930,3285 10180,3285 10435,3285 ; 9680,3385 9930,3385 10180,3385 10435,3385 ; 9680,3485 9930,3485 10180,3485 10435,3485 ; 9680,3585 9930,3585 10180,3585 10435,3585 ; 9680,3685 9930,3685 10180,3685 10435,3685 ; 9785,3980 9785,4225 9785,4475 ; 9799,1085 9799,1330 9799,1580 ; 9885,3980 9885,4225 9885,4475 ; 9899,1085 9899,1330 9899,1580 ; 9985,3980 9985,4225 9985,4475 ; 9999,1085 9999,1330 9999,1580 ; 10085,3980 10085,4225 10085,4475 ; 10099,1085 10099,1330 10099,1580 ; 10185,3980 10185,4225 10185,4475 ; 10199,1085 10199,1330 10199,1580 ; 10285,3980 10285,4225 10285,4475 ; 10299,1085 10299,1330 10299,1580 ; 10374.25,6030.87 10420.12,5985 11054.25,5985 11054.25,6095 11289.25,6095 11514.25,6095 11514.25,6690 ; 10385,3980 10385,4225 10385,4475 ; 10399,1085 10399,1330 10399,1580 ; 10424.25,6615 10424.25,6505 10814.25,6505 10814.25,6480 10889.25,6480 ; 10424.25,6715 10424.25,6765 10709.25,6765 10709.25,6694.57 10719.25,6694.57 ; 10485,3980 10485,4225 10485,4475 ; 10499,1085 10499,1330 10499,1580 ; 10524.25,6715 10644.25,6715 10644.25,6575 ; 10524.25,6815 10624.25,6815 ; 10585,3980 10585,4225 10585,4475 ; 10599,1085 10599,1330 10599,1580 ; v1(10669.25,6205.87) 11359.25,6205.87 11359.25,6295 ; 10669.25,6405 11009.25,6405 11009.25,6765.43 11014.25,6765.43 ; 10685,3980 10685,4225 10685,4475 ; 10699,1085 10699,1330 10699,1580 ; 10719.25,6060 10464.25,6060 10444.25,6080 10444.25,6420 10254.25,6420 10254.25,7675 10936.1,7675 ; 10724.25,6910 10424.25,6910 10424.25,6815 10344.25,6815 10344.25,6460 10489.25,6460 10489.25,6330 11064.25,6330 11064.25,6435 ; 10785,3980 10785,4225 10785,4475 ; 10799,1085 10799,1330 10799,1580 ; 10834.25,6605 10834.25,6875 11214.25,6875 11214.25,6970 ; 10885,3980 10885,4225 10885,4475 ; 10899,1085 10899,1330 10899,1580 ; 10985,3980 10985,4225 10985,4475 ; 10999,1085 10999,1330 10999,1580 ; 11035,1785 11285,1785 11530,1785 11780,1785 ; 11035,1885 11285,1885 11530,1885 11780,1885 ; 11035,1985 11285,1985 11530,1985 11780,1985 ; 11035,2085 11285,2085 11530,2085 11780,2085 ; 11035,2185 11285,2185 11530,2185 11780,2185 ; 11035,2285 11285,2285 11530,2285 11780,2285 ; 11035,2385 11285,2385 11530,2385 11780,2385 ; 11035,2485 11285,2485 11530,2485 11780,2485 ; 11035,2585 11285,2585 11530,2585 11780,2585 ; 11035,2685 11285,2685 11530,2685 11780,2685 ; 11035,2785 11285,2785 11530,2785 11780,2785 ; 11035,2885 11285,2885 11530,2885 11780,2885 ; 11035,2985 11285,2985 11530,2985 11780,2985 ; 11035,3085 11285,3085 11530,3085 11780,3085 ; 11035,3185 11285,3185 11530,3185 11780,3185 ; 11035,3285 11285,3285 11530,3285 11780,3285 ; 11035,3385 11285,3385 11530,3385 11780,3385 ; 11035,3485 11279,3485 ; 11035,3585 11285,3585 11530,3585 11780,3585 ; 11035,3685 11285,3685 11530,3685 11780,3685 ; 11042.4,7750 11042.4,7270 11514.25,7270 11514.25,6690 ; 11085,3980 11085,4225 11085,4475 ; 11099,1085 11099,1330 11099,1580 ; 11154.25,7765 11484.25,7765 11484.25,7565 11749.25,7565 11749.25,6490 11639.25,6490 ; 11185,3980 11185,4225 11185,4475 ; 11199,1085 11199,1330 11199,1580 ; 11285,3485 11530,3485 11780,3485 ; 11285,3980 11285,4225 11285,4475 ; 11299,1085 11299,1330 11299,1580 ; 11385,3980 11385,4225 11385,4475 ; 11399,1085 11399,1330 11399,1580 ; 11485,3980 11485,4225 11485,4475 ; 11499,1085 11499,1330 11499,1580 ; 11585,3980 11585,4225 11585,4475 ; 11599,1085 11599,1330 11599,1580 ; 11674.25,6755 11674.25,6690 11514.25,6690 ; 11685,3980 11685,4225 11685,4475 ; 11699,1085 11699,1330 11699,1580 ; v1(11704.25,5015) 11662.99,5015 11662.99,5368.31 11744.25,5368.31 ; 11744.25,5168.31 11744.25,5055 12144.25,5055 v1(12144.25,4920) ; 11849.25,5168.31 11852.56,5165 11857.56,5170 v1@11962.56,5170 ; 11864.25,6605 12204.25,6605 12204.25,7775 ; 11960,1590 12005,1635 12005,1810 11980,1835 11950,1835 11915.47,1869.53 11915.47,1915.47 11938,1938 11977,1938 12220,2181 12220,2365 ; 11960,1690 11915,1735 11915,1773.61 11895.47,1793.14 11895.47,1935 11915,1954.53 11915,2360 11970,2415 12150,2415 12165,2430 12165,2570 12220,2625 ; 11960,1890 12265,2195 12265,3110 12215,3160 ; v1(11999.25,4805) v1(12144.25,4805) ; 12115,3525 12070,3480 12070,3305 12115,3260 12070,3215 12070,3040 12115,2995 12160,2950 12160,2765 12120,2725 12075,2680 12075,2510 12120,2465 ; 5143,7668 5143,7650 5125,7650 5143,7668 ; 7322.19,3855 7401.19,3780 ; 7322.19,3855 7326.19,3855 7401.19,3780
  Bottom Layer w30: 1180,4250 1550,4250 1550,3805 1916.57,3805 ; 1185,4065 1415,4065 1415,3705 2113.43,3705 2113.43,3805 ; 1285,4225 v1@1285,4265
  other v1: 1280,4250 11967.56,5170
  other v2: 11210.94,6491.69 11254.25,6491.69 11297.56,6491.69 11210.94,6535 11297.56,6535 11210.94,6578.31 11254.25,6578.31 11297.56,6578.31

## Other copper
Top Layer:
  region: 1200,4225 1200,4355 1120,4355 1120,4225
  region: 1280,5195 1280,5275 1200,5275 1200,5195
  rectangle: 2605,2870 2745,2950
  rectangle: 1050,1670 1165,1790
  rectangle: 1320,1100 1435,1215
  text "530 (mil)" at 4579.08,5026.04 h60
  text "100 (mil)" at 5214.07,5026.04 h60
  text "530 (mil)" at 5839.08,5026.04 h60
  text "100 (mil)" at 6474.07,5026.04 h60
  text "530 (mil)" at 7099.08,5026.04 h60
Bottom Layer:
  region: 1190,4005 1190,4110 1115,4110 1115,4005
